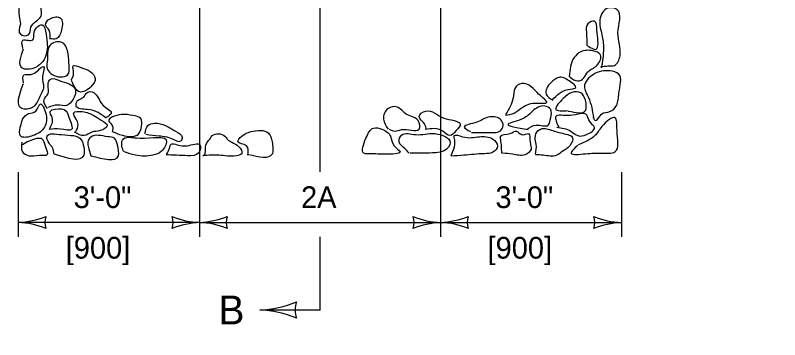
# Model space of a CAD drawing. Extents: x 49991.4 to 50021, y 49987.6 to 50011.4.
# Drawn here: x 50000.456 to 50002.571, y 49992.546 to 49993.444 of the extents above; entities that cross this region are included whole.
import ezdxf

# ---------------------------------------------------------------- set-up
doc = ezdxf.new("R2010")
doc.units = 0
for name, color, linetype in [('Level 1', 7, 'Continuous'), ('Level 2', 7, 'Continuous'), ('Level 3', 7, 'Continuous'), ('Level 6', 7, 'Continuous')]:
    doc.layers.add(name, color=color, linetype=linetype)

msp = doc.modelspace()

# ---------------------------------------------------------------- linework, layer by layer
at = {"layer": 'Level 1'}
for points in [[(50000.4702, 49993.4196), (50000.4757, 49993.4821), (50000.5035, 49993.4821), (50000.5216, 49993.4891), (50000.5271, 49993.4682), (50000.5271, 49993.4419), (50000.4994, 49993.4113), (50000.4924, 49993.3904), (50000.4702, 49993.3918), (50000.4702, 49993.4196)], [(50002.0747, 49993.3015), (50002.0956, 49993.3043), (50002.1136, 49993.3057), (50002.1289, 49993.3321), (50002.1233, 49993.396), (50002.1206, 49993.4599), (50002.0956, 49993.4641), (50002.0733, 49993.4321), (50002.0789, 49993.3904), (50002.0831, 49993.3529), (50002.0775, 49993.2988)], [(50000.5521, 49993.3779), (50000.5494, 49993.4029), (50000.5396, 49993.4182), (50000.5521, 49993.4349), (50000.5813, 49993.4363), (50000.5841, 49993.4043), (50000.5688, 49993.3793), (50000.5535, 49993.3793)], [(50002.0386, 49993.3599), (50002.065, 49993.3516), (50002.0678, 49993.3724), (50002.065, 49993.4043), (50002.0581, 49993.4279), (50002.04, 49993.421), (50002.0358, 49993.3974), (50002.0372, 49993.3599)], [(50000.4771, 49993.3529), (50000.4771, 49993.3752), (50000.5049, 49993.3766), (50000.5077, 49993.3918), (50000.5146, 49993.4099), (50000.5299, 49993.4182), (50000.541, 49993.3918), (50000.5424, 49993.339), (50000.5119, 49993.3001), (50000.4743, 49993.2988), (50000.4785, 49993.3516)], [(50000.5452, 49993.3224), (50000.5452, 49993.2946), (50000.5577, 49993.2807), (50000.5813, 49993.2738), (50000.6008, 49993.2793), (50000.6049, 49993.3057), (50000.6021, 49993.3376), (50000.5869, 49993.3682), (50000.5549, 49993.3641), (50000.5452, 49993.321)], [(50001.99, 49993.2738), (50002.0122, 49993.2626), (50002.0289, 49993.271), (50002.04, 49993.2876), (50002.065, 49993.3057), (50002.0747, 49993.3349), (50002.0539, 49993.346), (50002.0205, 49993.3432), (50002.0025, 49993.3279), (50001.9886, 49993.2738)], [(50000.4785, 49993.2571), (50000.4799, 49993.2793), (50000.4994, 49993.2807), (50000.5188, 49993.2918), (50000.5341, 49993.3029), (50000.5313, 49993.2751), (50000.5341, 49993.246), (50000.5216, 49993.2154), (50000.5035, 49993.189), (50000.4743, 49993.1862), (50000.4785, 49993.2557)], [(50000.6105, 49993.2654), (50000.6174, 49993.2835), (50000.616, 49993.3043), (50000.6369, 49993.3001), (50000.6633, 49993.289), (50000.6772, 49993.2696), (50000.6647, 49993.246), (50000.6341, 49993.2321), (50000.6119, 49993.264)], [(50002.0539, 49993.1626), (50002.0608, 49993.1529), (50002.0775, 49993.1709), (50002.1011, 49993.1779), (50002.1192, 49993.1946), (50002.1261, 49993.2293), (50002.1247, 49993.2821), (50002.1011, 49993.2904), (50002.0553, 49993.2807), (50002.0303, 49993.2474), (50002.0414, 49993.2168), (50002.0553, 49993.1612)], [(50000.5452, 49993.1862), (50000.5355, 49993.2112), (50000.5466, 49993.2279), (50000.548, 49993.2599), (50000.5549, 49993.2682), (50000.5771, 49993.264), (50000.6049, 49993.2543), (50000.6216, 49993.2404), (50000.616, 49993.2126), (50000.598, 49993.1946), (50000.573, 49993.196), (50000.5466, 49993.189)], [(50001.8122, 49993.1682), (50001.8358, 49993.1737), (50001.858, 49993.189), (50001.9011, 49993.2015), (50001.9261, 49993.2029), (50001.9038, 49993.2265), (50001.8886, 49993.2418), (50001.8636, 49993.2557), (50001.8413, 49993.2474), (50001.8344, 49993.2224), (50001.8274, 49993.1973), (50001.8122, 49993.1696)], [(50001.9414, 49993.2099), (50001.9608, 49993.2279), (50001.9844, 49993.239), (50002.0066, 49993.2446), (50001.9886, 49993.2626), (50001.9594, 49993.2724), (50001.9386, 49993.2585), (50001.9261, 49993.2418), (50001.9247, 49993.2265), (50001.9427, 49993.2099)], [(50000.7077, 49993.1598), (50000.6855, 49993.1751), (50000.6549, 49993.1835), (50000.6244, 49993.1932), (50000.6285, 49993.2085), (50000.6452, 49993.2182), (50000.6522, 49993.2279), (50000.6619, 49993.2335), (50000.6841, 49993.2182), (50000.6994, 49993.1946), (50000.7216, 49993.1737), (50000.7077, 49993.1612)], [(50001.9858, 49993.1793), (50002.033, 49993.1807), (50002.033, 49993.2099), (50002.0205, 49993.2293), (50001.9955, 49993.2307), (50001.9719, 49993.214), (50001.9511, 49993.1848), (50001.9858, 49993.1807)], [(50000.4757, 49993.1571), (50000.4924, 49993.1723), (50000.5132, 49993.1793), (50000.5244, 49993.1987), (50000.541, 49993.1696), (50000.5341, 49993.1307), (50000.5049, 49993.1112), (50000.473, 49993.1084), (50000.4771, 49993.1584)], [(50001.4899, 49993.1293), (50001.5065, 49993.1237), (50001.5246, 49993.1279), (50001.5524, 49993.1265), (50001.5732, 49993.1293), (50001.5704, 49993.1529), (50001.5371, 49993.1709), (50001.5121, 49993.1904), (50001.4871, 49993.1862), (50001.4746, 49993.1571), (50001.4871, 49993.1293)], [(50001.8719, 49993.1293), (50001.8969, 49993.1404), (50001.9302, 49993.1404), (50001.9372, 49993.1612), (50001.9372, 49993.1835), (50001.9205, 49993.1932), (50001.8872, 49993.1793), (50001.8608, 49993.1584), (50001.8191, 49993.1432), (50001.8747, 49993.1279)], [(50000.5507, 49993.1293), (50000.5577, 49993.1612), (50000.5521, 49993.1779), (50000.566, 49993.1848), (50000.5966, 49993.1793), (50000.6049, 49993.1598), (50000.6119, 49993.1279), (50000.5813, 49993.1293), (50000.5494, 49993.1279)], [(50000.623, 49993.1209), (50000.6299, 49993.1418), (50000.6244, 49993.1571), (50000.6174, 49993.1737), (50000.6411, 49993.1779), (50000.673, 49993.1668), (50000.6938, 49993.1543), (50000.7105, 49993.139), (50000.6911, 49993.1251), (50000.6674, 49993.1209), (50000.6466, 49993.1112), (50000.6202, 49993.1209)], [(50000.7244, 49993.1223), (50000.7244, 49993.139), (50000.7147, 49993.1515), (50000.7494, 49993.1696), (50000.7814, 49993.1668), (50000.8036, 49993.1584), (50000.805, 49993.1376), (50000.7966, 49993.1154), (50000.7522, 49993.1126), (50000.7244, 49993.1223)], [(50001.5927, 49993.1279), (50001.5885, 49993.1432), (50001.5732, 49993.164), (50001.5913, 49993.1793), (50001.6163, 49993.1737), (50001.6413, 49993.1598), (50001.6705, 49993.1529), (50001.6871, 49993.1432), (50001.676, 49993.1251), (50001.658, 49993.1112), (50001.6385, 49993.1237), (50001.5899, 49993.1279)], [(50001.9539, 49993.1348), (50001.9928, 49993.1237), (50002.0122, 49993.1112), (50002.0358, 49993.114), (50002.0581, 49993.1334), (50002.0455, 49993.1501), (50002.0372, 49993.1682), (50001.9914, 49993.1668), (50001.9511, 49993.164), (50001.9594, 49993.1348)], [(50001.7177, 49993.1196), (50001.7663, 49993.1196), (50001.801, 49993.1279), (50001.8052, 49993.1432), (50001.7969, 49993.1571), (50001.7649, 49993.1626), (50001.733, 49993.1487), (50001.6982, 49993.1348), (50001.7149, 49993.1223)], [(50002.0122, 49993.0848), (50001.9941, 49993.0626), (50002.033, 49993.0612), (50002.0775, 49993.0626), (50002.115, 49993.0668), (50002.1206, 49993.1265), (50002.115, 49993.1612), (50002.0789, 49993.1362), (50002.0594, 49993.1112), (50002.0136, 49993.0862)], [(50000.8147, 49993.1168), (50000.823, 49993.139), (50000.8411, 49993.1459), (50000.8717, 49993.139), (50000.8994, 49993.1237), (50000.9175, 49993.1057), (50000.9133, 49993.0959), (50000.8911, 49993.1015), (50000.8536, 49993.1098), (50000.8175, 49993.114)], [(50001.0995, 49993.057), (50001.0953, 49993.0834), (50001.0717, 49993.0945), (50001.0828, 49993.1098), (50001.1078, 49993.1223), (50001.1565, 49993.1182), (50001.1662, 49993.0945), (50001.1662, 49993.0598), (50001.1009, 49993.0584)], [(50001.4635, 49993.0598), (50001.4426, 49993.0612), (50001.4204, 49993.0626), (50001.426, 49993.1043), (50001.4468, 49993.1321), (50001.4704, 49993.1293), (50001.494, 49993.1098), (50001.5038, 49993.0834), (50001.5204, 49993.0668), (50001.4801, 49993.0598), (50001.4607, 49993.0598)], [(50001.8955, 49993.0598), (50001.8969, 49993.0876), (50001.8941, 49993.1057), (50001.9025, 49993.1251), (50001.9136, 49993.1307), (50001.9469, 49993.1237), (50001.9844, 49993.114), (50001.9969, 49993.1071), (50001.99, 49993.0834), (50001.9705, 49993.0681), (50001.9539, 49993.057), (50001.9163, 49993.057), (50001.8955, 49993.0584)], [(50000.5633, 49993.0598), (50000.5591, 49993.0779), (50000.5494, 49993.0904), (50000.5438, 49993.1098), (50000.5841, 49993.114), (50000.6383, 49993.1001), (50000.6452, 49993.0806), (50000.6452, 49993.057), (50000.5646, 49993.0598)], [(50000.6647, 49993.0556), (50000.6577, 49993.082), (50000.6577, 49993.0973), (50000.6647, 49993.1071), (50000.7119, 49993.1084), (50000.73, 49993.1043), (50000.7383, 49993.0862), (50000.7411, 49993.0556), (50000.6647, 49993.0556)], [(50000.7564, 49993.0668), (50000.7508, 49993.082), (50000.7522, 49993.0987), (50000.8008, 49993.1043), (50000.8744, 49993.0959), (50000.8605, 49993.0681), (50000.8369, 49993.057), (50000.7883, 49993.057), (50000.7577, 49993.0668)], [(50000.9745, 49993.0543), (50000.9814, 49993.0626), (50000.9828, 49993.0848), (50000.9939, 49993.1015), (50001.0009, 49993.1112), (50001.0356, 49993.1098), (50001.0425, 49993.1015), (50001.055, 49993.0931), (50001.0745, 49993.0806), (50001.0828, 49993.0626), (50001.0675, 49993.0556), (50001.0203, 49993.057), (50000.9745, 49993.0556)], [(50001.5454, 49993.0626), (50001.5343, 49993.0751), (50001.5176, 49993.0945), (50001.5246, 49993.1126), (50001.5635, 49993.114), (50001.6177, 49993.1168), (50001.6593, 49993.0918), (50001.6427, 49993.0695), (50001.6191, 49993.064), (50001.5482, 49993.0626)], [(50001.6621, 49993.0556), (50001.6691, 49993.0751), (50001.6718, 49993.0987), (50001.6705, 49993.1112), (50001.6927, 49993.1084), (50001.7399, 49993.1084), (50001.7774, 49993.1015), (50001.7899, 49993.082), (50001.7774, 49993.0654), (50001.7538, 49993.0612), (50001.6968, 49993.057), (50001.6621, 49993.0543)], [(50001.8024, 49993.0626), (50001.801, 49993.0765), (50001.7996, 49993.0959), (50001.7983, 49993.1098), (50001.8247, 49993.1168), (50001.8427, 49993.1237), (50001.8566, 49993.114), (50001.8761, 49993.1168), (50001.8802, 49993.0931), (50001.883, 49993.0737), (50001.8663, 49993.0584), (50001.8316, 49993.0598), (50001.8038, 49993.0626)], [(50000.4743, 49993.0931), (50000.4757, 49993.0668), (50000.4938, 49993.0556), (50000.523, 49993.057), (50000.5452, 49993.0598), (50000.541, 49993.0765), (50000.5285, 49993.1029), (50000.5146, 49993.1029), (50000.4757, 49993.0862)], [(50000.8744, 49993.0598), (50000.8828, 49993.0765), (50000.8869, 49993.0876), (50000.9036, 49993.0862), (50000.9314, 49993.0834), (50000.9675, 49993.0848), (50000.9633, 49993.064), (50000.9328, 49993.0556), (50000.873, 49993.0584)], [(50002.2619, 49991.3557), (50002.3349, 49991.3922), (50002.4238, 49991.4367), (50002.5291, 49991.5121), (50002.6072, 49991.52), (50002.7666, 49991.6222), (50002.9299, 49991.6979), (50003.0239, 49991.7534), (50003.1684, 49991.8089), (50003.2652, 49991.8664), (50003.4173, 49991.9368), (50003.5346, 49992.0036), (50003.7319, 49992.1001), (50003.896, 49992.1823), (50004.0361, 49992.2633), (50004.183, 49992.3286), (50004.3686, 49992.4424), (50004.513, 49992.5091), (50004.5584, 49992.5497), (50004.7647, 49992.6283), (50004.8545, 49992.6869), (50004.9836, 49992.7492), (50005.0555, 49992.7804)]]:
    msp.add_spline(points, degree=3, dxfattribs=at)
at = {"layer": 'Level 3'}
for p, q in [((50000.9657, 49993.9992), (50000.9657, 49992.8309)), ((50001.6325, 49993.9992), (50001.6325, 49992.8309)), ((50000.4642, 49993.0099), (50000.4642, 49992.8312)), ((50002.1326, 49993.0099), (50002.1326, 49992.8309)), ((50000.9657, 49992.8709), (50000.4642, 49992.8709)), ((50000.9657, 49992.8709), (50001.6325, 49992.8709)), ((50001.6325, 49992.8709), (50002.1326, 49992.8709))]:
    msp.add_line(p, q, dxfattribs=at)
for centre, radius, start, end in [((50000.4527, 49993.1036), 0.233, 272.8273, 292.0772), ((50000.5924, 49992.8709), 0.0548, 162.1388, 197.8612), ((50000.9749, 49993.093), 0.2223, 247.456, 267.6395), ((50000.8375, 49992.8709), 0.0548, 342.1388, 17.8612), ((50000.9543, 49993.1036), 0.233, 272.8273, 292.0772), ((50001.094, 49992.8709), 0.0548, 162.1388, 197.8612), ((50001.6417, 49993.093), 0.2223, 247.456, 267.6395), ((50001.5043, 49992.8709), 0.0548, 342.1388, 17.8612), ((50001.6211, 49993.1036), 0.233, 272.8273, 292.0772), ((50001.7608, 49992.8709), 0.0548, 162.1388, 197.8612), ((50002.1418, 49993.093), 0.2223, 247.456, 267.6395), ((50002.0044, 49992.8709), 0.0548, 342.1388, 17.8612), ((50000.455, 49992.6488), 0.2223, 67.456, 87.6395), ((50000.9772, 49992.6382), 0.233, 92.8273, 112.0772), ((50000.9566, 49992.6488), 0.2223, 67.456, 87.6395), ((50001.644, 49992.6382), 0.233, 92.8273, 112.0772), ((50001.6234, 49992.6488), 0.2223, 67.456, 87.6395), ((50002.1441, 49992.6382), 0.233, 92.8273, 112.0772), ((50001.3034, 49992.6287), 0.073, 162.1388, 197.8612)]:
    msp.add_arc(centre, radius, start, end, dxfattribs=at)
at = {"layer": 'Level 6'}
for p, q in [((50001.2991, 49993.0109), (50001.2991, 49996.4249)), ((50001.2991, 49992.6287), (50001.2991, 49992.8309)), ((50001.2991, 49992.6287), (50001.1324, 49992.6287))]:
    msp.add_line(p, q, dxfattribs=at)
for centre, radius, start, end in [((50001.1171, 49992.939), 0.3107, 272.8273, 292.0772), ((50001.1202, 49992.3325), 0.2964, 67.456, 87.6395)]:
    msp.add_arc(centre, radius, start, end, dxfattribs=at)

# ---------------------------------------------------------------- texts
at = {"layer": 'Level 2'}
for s, height, p in [('3\'-0"', 0.06, (50000.6174, 49992.9109)), ('2A', 0.06, (50001.2465, 49992.9109)), ('3\'-0"', 0.06, (50001.7843, 49992.9109)), ('[900] ', 0.06, (50000.5956, 49992.7709)), ('[900] ', 0.06, (50001.7625, 49992.7709)), ('B', 0.08, (50001.0184, 49992.5887))]:
    msp.add_text(s, height=height, dxfattribs=at).set_placement(p)

doc.saveas('drawing.dxf')
